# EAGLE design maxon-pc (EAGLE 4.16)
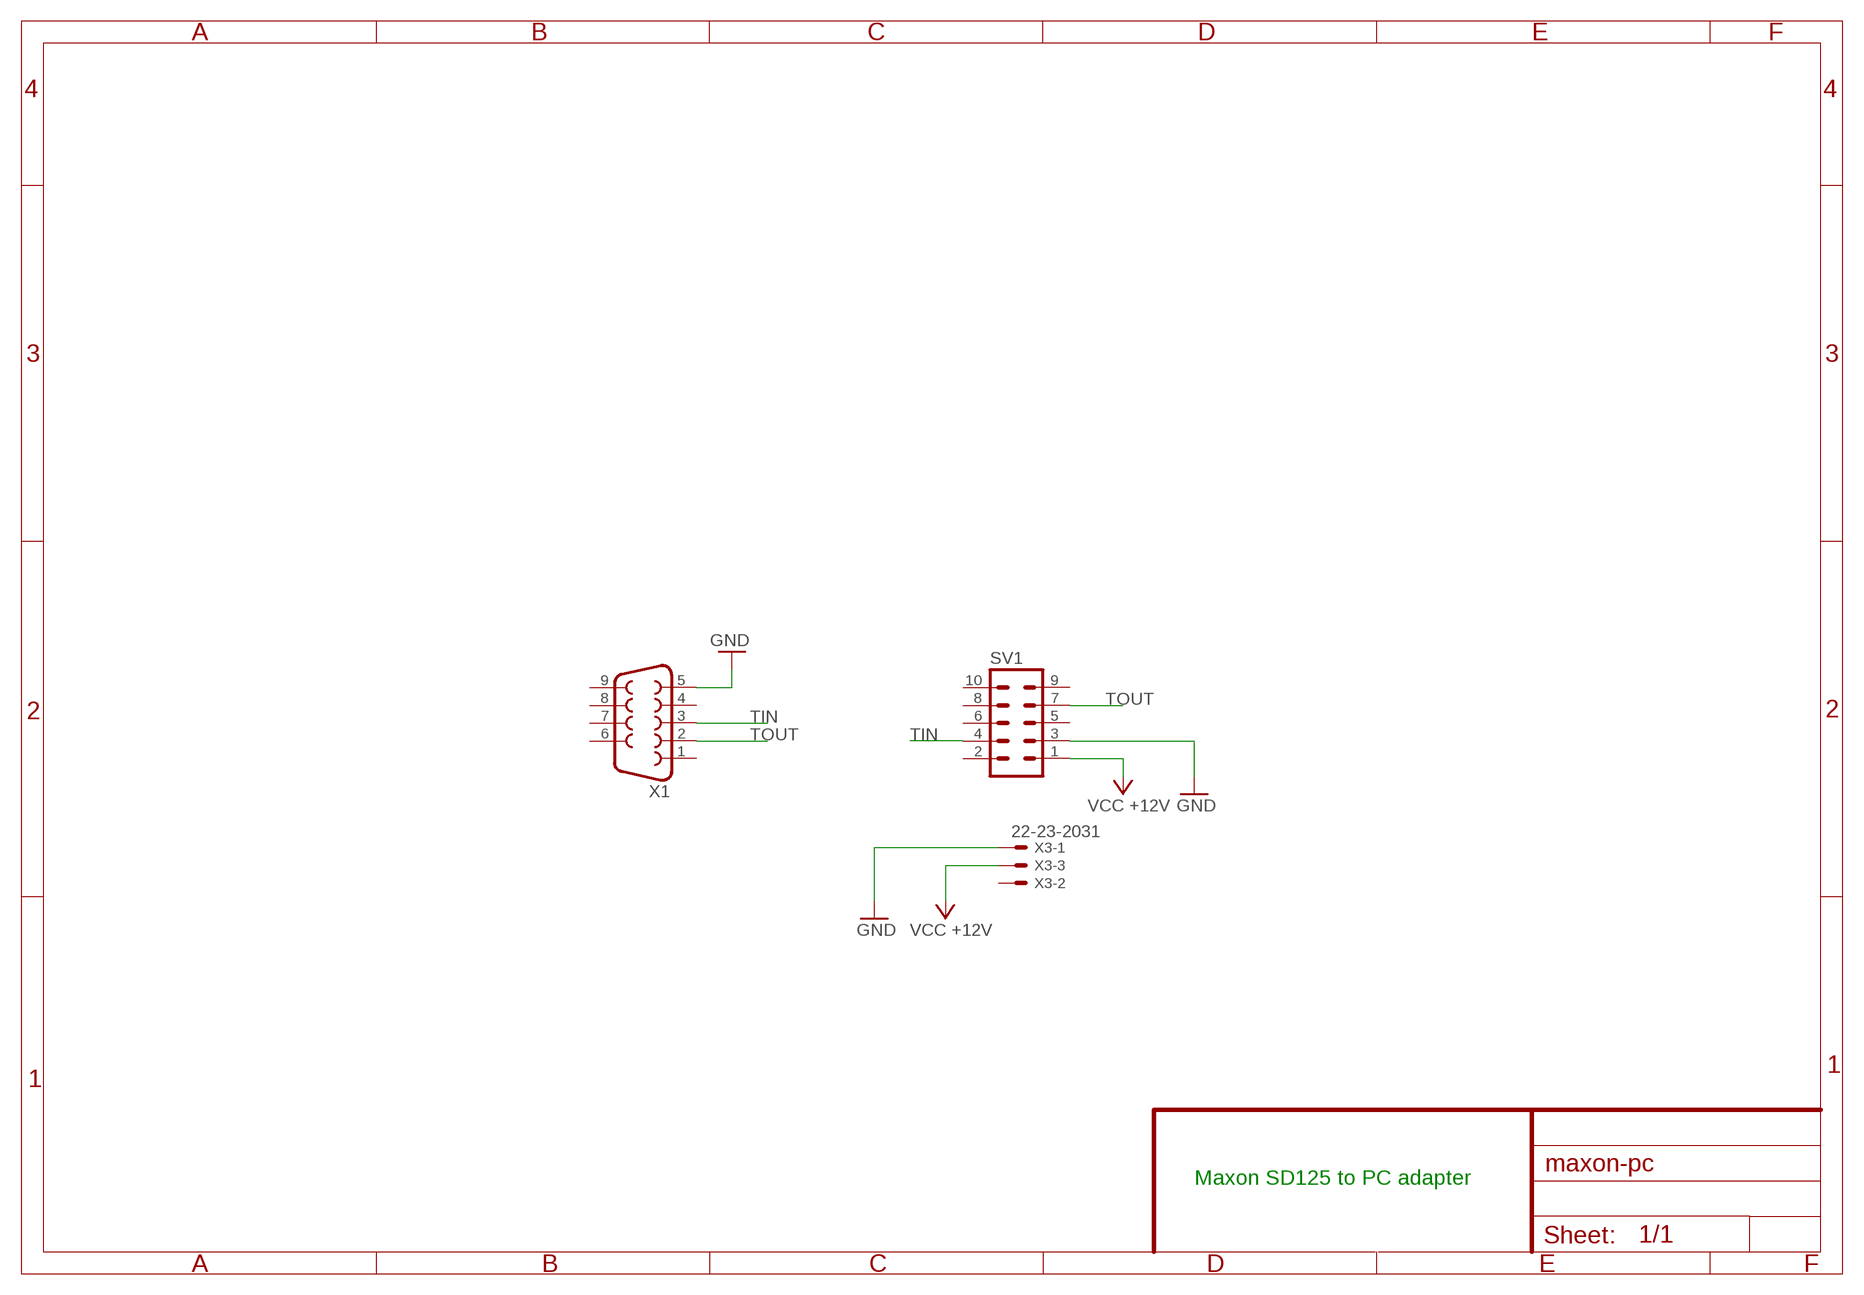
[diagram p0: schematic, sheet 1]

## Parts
SV1  MA05-2  [MA05-2]
X1  F09HP  [F09HP]
X3  22-23-2031  [22-23-2031]

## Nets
GND: SV1.3 X1.5 X3.1
TIN: SV1.4 X1.3
TOUT: SV1.7 X1.2
VCC: SV1.1 X3.3 ; supply symbol labelled VCC +12V
Unconnected: SV1.2 SV1.5 SV1.6 SV1.8 SV1.9 SV1.10 X1.1 X1.4 X1.6 X1.7 X1.8 X1.9 X3.2

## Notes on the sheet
- Maxon SD125 to PC adapter

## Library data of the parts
SV1 = con-lstb:MA05-2: PIN HEADER
X1 = con-subd:F09: SUB-D
X3 = con-molex:22-23-2031: .100" (2.54mm) Center Header - 3 Pin

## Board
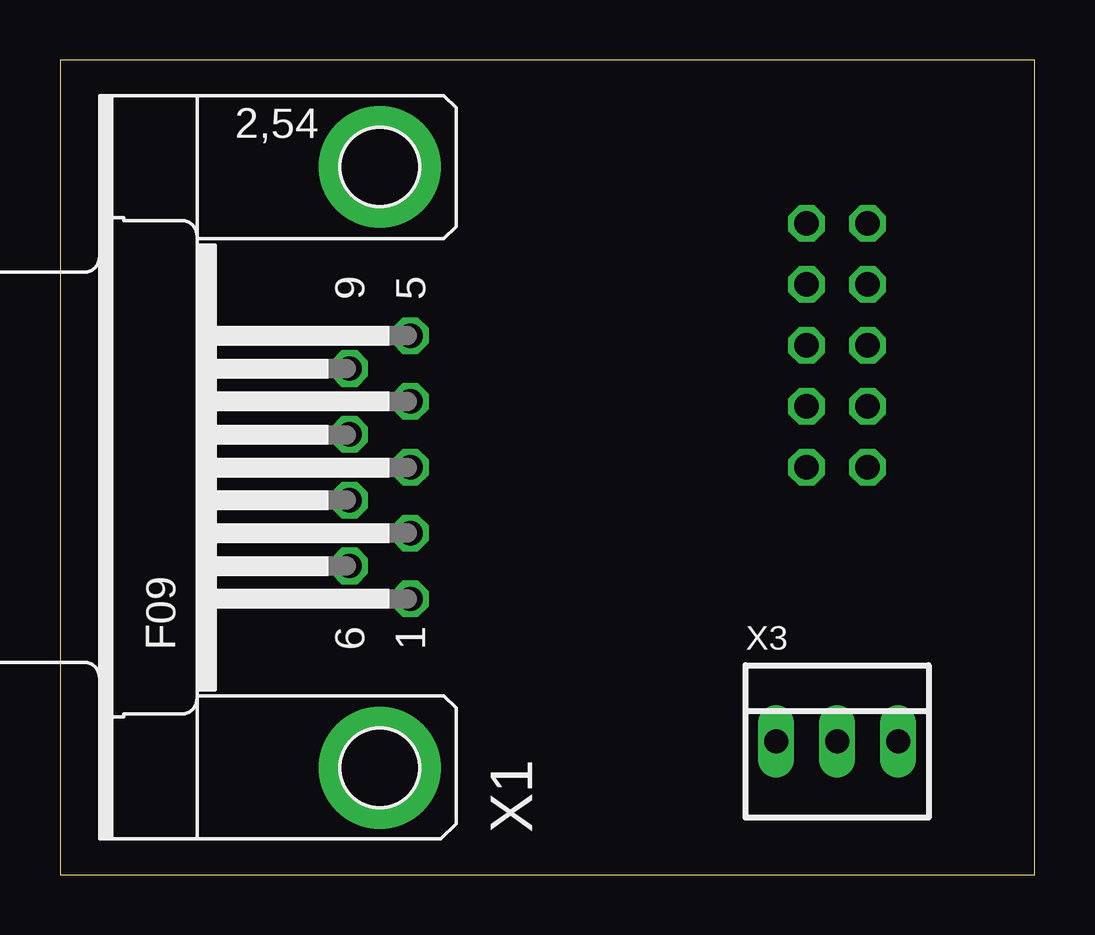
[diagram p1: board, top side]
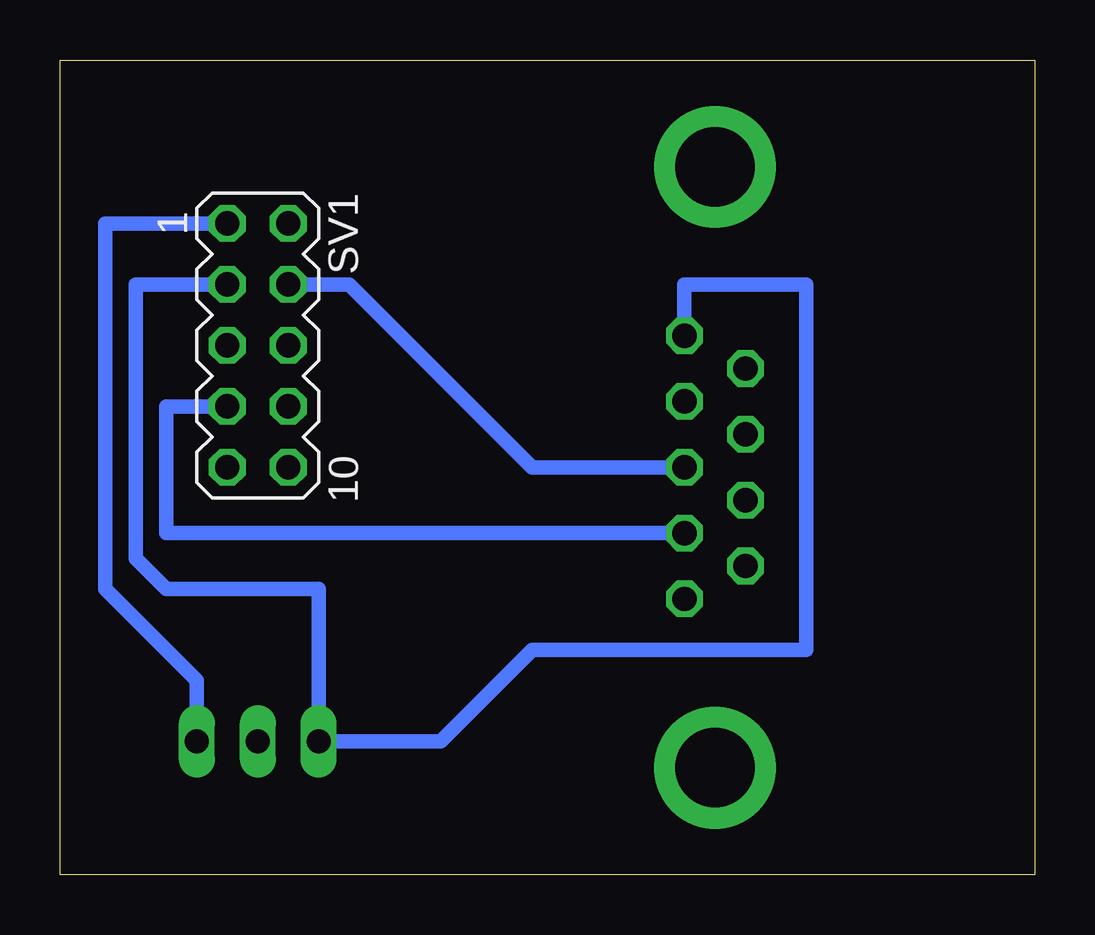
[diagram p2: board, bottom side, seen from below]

Size 40.62 x 33.96 mm. Coordinates in mm from the lower left corner, seen from the top.
Outline: 0,0 40.62,0 40.62,33.96 0,33.96 0,0
Copper layers (1*16): Top 0.035mm / dielectric 1.5mm / Bottom 0.035mm
Design rules "default": minimum track width 10mil, minimum drill 24mil, track to track 8mil, track to pad 8mil, pad to pad 8mil, via to via 8mil, smd to smd 8mil, copper to edge 40mil, drill to drill 8mil, minimum pad ring 10mil, minimum via ring 8mil, stop-mask expansion 4mil, vias tented up to drill 0mil, thermal gap 10mil

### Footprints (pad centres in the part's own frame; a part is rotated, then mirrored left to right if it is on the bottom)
MA05-2 = drill 1.016 octagon: 1 -5.08,-1.27; 2 -5.08,1.27; 3 -2.54,-1.27; 4 -2.54,1.27; 5 0,-1.27; 6 0,1.27; 7 2.54,-1.27; 8 2.54,1.27; 9 5.08,-1.27; 10 5.08,1.27
F09HP = drill 1.016 octagon: 1 -5.486,-1.27; 2 -2.743,-1.27; 3 0,-1.27; 4 2.743,-1.27; 5 5.486,-1.27; 6 -4.115,1.27; 7 -1.372,1.27; 8 1.372,1.27; 9 4.115,1.27 | drill 3.302 pad 5.08 round: G1 -12.522,0; G2 12.522,0
22-23-2031 = drill 1 long: 1 -2.54,0; 2 0,0; 3 2.54,0

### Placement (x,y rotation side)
SV1  32.38,22.06 270 bottom
X1  13.33,16.98 90 top
X3  32.38,5.55 0 top

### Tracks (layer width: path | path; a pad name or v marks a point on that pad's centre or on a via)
GND
  Bottom 0.61: X1.5 14.6,24.6 9.52,24.6 9.52,9.36 20.95,9.36 24.76,5.55 X3.1 29.84,11.9 36.19,11.9 37.46,13.17 37.46,24.6 SV1.3
TIN
  Bottom 0.61: X1.3 20.95,16.98 28.57,24.6 SV1.4
TOUT
  Bottom 0.61: X1.2 36.19,14.24 36.19,19.52 SV1.7
VCC
  Bottom 0.61: SV1.1 38.73,27.14 38.73,11.9 34.92,8.09 X3.3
